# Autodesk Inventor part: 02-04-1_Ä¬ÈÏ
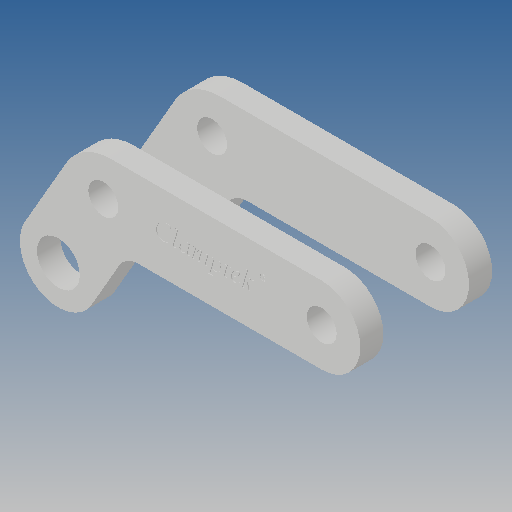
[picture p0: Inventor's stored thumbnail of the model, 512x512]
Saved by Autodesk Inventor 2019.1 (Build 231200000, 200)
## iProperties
Created: 2010-06
Part Number: 02-04-1_Ä¬ÈÏ
Material: Ogólny
Document SubType Name: Modeling
Designer: CADENGINEERING4
Density: 1 g/cm^3
Appearance: Domyślna
Author: CADENGINEERING4
Revision Number: ÈÎºÎ
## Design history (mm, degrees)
feature "NONE"
feature "NONE:1"
node "Bryła1"
node "Bryła2"
